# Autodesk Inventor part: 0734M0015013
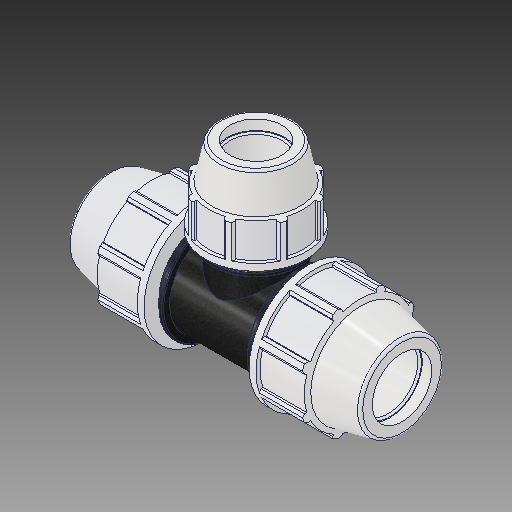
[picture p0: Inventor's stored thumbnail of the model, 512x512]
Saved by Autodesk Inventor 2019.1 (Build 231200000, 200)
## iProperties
Created: 2017-02
Part Number: 0734M0015013
Material: PVC-Piping
Description: PLASSON REDUCING TEE 1 1/2'' - 1 1/4'' - 1 1/2''
Document SubType Name: Modeling
Designer: KIM
Mass: 92.6774 g
Surface Area: 199.44 cm^2
Volume: 66.1981 cm^3
Density: 1.4 g/cm^3
Appearance: PTFE
Author: Кирилл
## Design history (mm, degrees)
derived "0734M0.ipt"
feature "Solid1::0734M0.ipt"
feature "Solid2::0734M0.ipt"
tag "TaggingFeature1"
body "Solid1"
other parameters: "d2" = 48.1, "d4" = 9.83192, "d5" = 33.03524, "d7" = 96.012, "d11" = 3.93277, "d13" = 120 deg, "d14" = 67.34, "d15" = 12 deg, "d16" = 83.53044, "d18" = 2.405, "d19" = 35 deg, "d20" = 17.5 deg, "d21" = 89.29116, "d23" = 0, "d25" = 360 deg, "d27" = 1.92024, "d33" = 0.962, "d42" = 42.47388, "d43" = 2.88036, "d46" = 1.443, "d67" = 72.009, "d76" = 42.1, "d77" = 82.042, "d78" = 12 deg, "d79" = 114.046, "d80" = 120 deg, "d81" = 58.94, "d82" = 9.50383, "d87" = 3.80153, "d89" = 28.5115, "d90" = 34.2138, "d96" = 19.66383, "d98" = 76.29906, "d99" = 35 deg, "d100" = 17.5 deg, "d102" = 0, "d103" = 1.64084, "d107" = 360 deg, "d109" = 1.263, "d112" = 2.105, "d113" = 5.46947, "d114" = 0, "d117" = 235.966, "d118" = 71.37654, "d126" = 43.29, "d127" = 92.964, "d131" = 4.56184, "d132" = 37.89, "d133" = 82.042, "d135" = 0, "d138" = 4.71932, "d143" = 0, "d148" = 61.5315, "d168" = 43.29, "d170" = 0, "d171" = 42.1, "d173" = 0, "d176" = 5.46947, "d177" = 0, "d_" = 48.1, "E_" = 96.012, "A_" = 114.046, "l_" = 92.964, "E_1" = 82.042, "l_1" = 82.042, "d_1" = 42.1, "H_" = 235.966
